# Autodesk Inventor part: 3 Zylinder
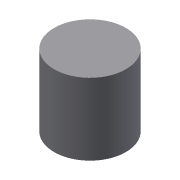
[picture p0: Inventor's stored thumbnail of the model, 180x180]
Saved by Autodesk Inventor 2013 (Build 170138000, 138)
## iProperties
Created: 2012-10
Part Number: 3 Zylinder
Material: Allgemein
Vendor: www.inventor-faq.de
Document SubType Name: Modeling
Designer: Administrator
Manufacturer: www.inventor-faq.de
Density: 1 g/cm^3
RuleStatus: InUse
AfterDocOpen0: inventorfaq
BeforeDocSave0: inventorfaq
Author: Administrator
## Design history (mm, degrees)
sketch "Skizze1"
  geometry: C1 r 5 at (0, 0); 1 further point
  constraints: 1 centre point, 1 coincident
  dimensions: "d0" = 10 diameter of C1
extrude "Extrusion1" new body sketch "Skizze1" distance "d1" = 10; taper "d2" = 0 deg
node "Volumenkörper1"
